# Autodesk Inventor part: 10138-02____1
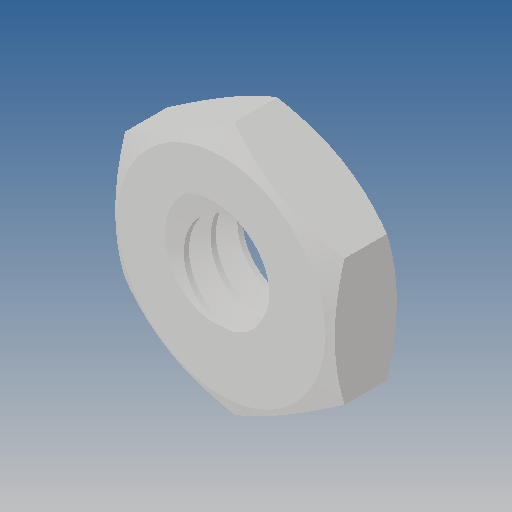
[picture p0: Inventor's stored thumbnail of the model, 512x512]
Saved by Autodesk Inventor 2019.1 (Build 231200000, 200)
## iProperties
Created: 2012-09
Part Number: 10138-02____1
Material: Ogólny
Document SubType Name: Modeling
Designer: CADENGINEERING4
Density: 1 g/cm^3
Appearance: Domyślna
Author: CADENGINEERING4
Revision Number: ÈÎºÎ
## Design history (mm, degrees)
feature "NONE"
node "Bryła1"
